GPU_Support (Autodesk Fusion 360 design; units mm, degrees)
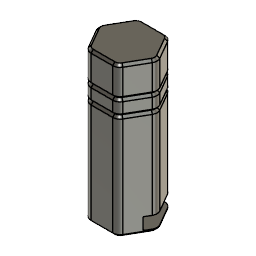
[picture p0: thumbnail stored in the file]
parameter "BodyL" = 28
parameter "HexR" = 7
parameter "Fillet" = 2
parameter "NutH" = 4
parameter "ThreadOffset" = 0.2
parameter "MagnetD" = 10
parameter "MagnetH" = 3
sketch "Sketch1" plane through (0, 0, 0) normal (0, 0, 1) x axis (1, 0, 0)
  line L1 (4.0415, 7) -> (8.0829, 0)
  line L2 (-4.0415, 7) -> (4.0415, 7)
  line L3 (-8.0829, 0) -> (-4.0415, 7)
  line L4 (-4.0415, -7) -> (-8.0829, 0)
  line L5 (4.0415, -7) -> (-4.0415, -7)
  line L6 (8.0829, 0) -> (4.0415, -7)
  line L7 (6.9744, -1.9201) -> (2.575, -4.46)
  line L8 (-2.575, 4.46) -> (1.8244, 7)
  circle C1 centre (0, 0) radius 5.15
  point P1 (0, 0)
  point P8 (0, 0)
  point P9 (0, 0)
  point P10 (2.575, -4.46)
  point P12 (1.8244, 7)
  point P11 (6.9744, -1.9201)
  coincident P1 P8
  horizontal L2
  coincident P1 P9
  coincident C1 P10
  tangent C1 L7
  coincident L2 P12
  parallel L7 L8
  equal L7 L8
  tangent C1 L8
  perpendicular L1 L7
  coincident L6 P11
  dimension "d1" distance P8 L6 = 7
  dimension "d36" diameter C1 = 10.3 (= "MagnetD + 0.3 mm")
extrude "Extrude1" new body sketch "Sketch1" profile of L1 L2 L3 L4 L5 L6 along normal blind 28 (= "BodyL")
fillet "Fillet1" radius 2 (= "Fillet")
sketch "Sketch1" plane through (0, 0, 28) normal (0, 0, 1) x axis (-1, 0, 0)
  line L1 (-7.5056, 1) -> (-4.6188, 6)
  line L2 (-4.6188, -6) -> (-7.5056, -1)
  line L3 (2.8868, -7) -> (-2.8868, -7)
  line L4 (7.5056, -1) -> (4.6188, -6)
  line L5 (4.6188, 6) -> (7.5056, 1)
  line L6 (-2.8868, 7) -> (2.8868, 7)
  arc A1 centre (5.7735, 0) radius 2 clockwise from (7.5056, 1) to (7.5056, -1)
  arc A2 centre (2.8868, 5) radius 2 clockwise from (2.8868, 7) to (4.6188, 6)
  arc A3 centre (-2.8868, 5) radius 2 clockwise from (-4.6188, 6) to (-2.8868, 7)
  arc A4 centre (-5.7735, 0) radius 2 clockwise from (-7.5056, -1) to (-7.5056, 1)
  arc A5 centre (-2.8868, -5) radius 2 clockwise from (-2.8868, -7) to (-4.6188, -6)
  arc A6 centre (2.8868, -5) radius 2 clockwise from (4.6188, -6) to (2.8868, -7)
extrude "Extrude1" new body sketch "Sketch1" profile of L1 L2 L3 L4 L5 L6 along normal blind 4 (= "NutH")
sketch "Sketch1" plane through (0, 0, 32) normal (0, 0, 1) x axis (-1, 0, 0)
  line L1 (7.5056, -1) -> (4.6188, -6)
  line L2 (4.6188, 6) -> (7.5056, 1)
  line L3 (-2.8868, 7) -> (2.8868, 7)
  line L4 (-7.5056, 1) -> (-4.6188, 6)
  line L5 (-4.6188, -6) -> (-7.5056, -1)
  line L6 (2.8868, -7) -> (-2.8868, -7)
  arc A1 centre (2.8868, -5) radius 2 clockwise from (4.6188, -6) to (2.8868, -7)
  arc A2 centre (5.7735, 0) radius 2 clockwise from (7.5056, 1) to (7.5056, -1)
  arc A3 centre (2.8868, 5) radius 2 clockwise from (2.8868, 7) to (4.6188, 6)
  arc A4 centre (-2.8868, 5) radius 2 clockwise from (-4.6188, 6) to (-2.8868, 7)
  arc A5 centre (-5.7735, 0) radius 2 clockwise from (-7.5056, -1) to (-7.5056, 1)
  arc A6 centre (-2.8868, -5) radius 2 clockwise from (-2.8868, -7) to (-4.6188, -6)
  circle C1 centre (0, 0) radius 4
  point P1 (0, 0)
  point P20 (0, 0)
  coincident P1 P20
  dimension "d14" diameter C1 = 8
extrude "Extrude1" new body sketch "Sketch1" profile of A1 L1 A2 L2 A3 L3 A4 L4 A5 L5 A6 L6 along normal blind 8
extrude "Extrude2" add sketch "Sketch1" profile of C1 against normal blind 27 (magnitude of "-BodyL + 1 mm")
thread "Thread1" ThreadOffset 0 ThreadLength 10
combine "Combine1"
combine "Combine1"
offset_faces "OffsetFaces1"
chamfer "Chamfer1" distance 0.6 distance 1
extrude "Extrude2" cut sketch "Sketch1" profile of L1 L2 L6 C1 L7 L8 blind 3.2 (= "MagnetH + 0.2 mm") from offset 0.8
sketch "Sketch2" plane through (-6.0622, -3.5, 0) normal (-0.866, -0.5, 0) x axis (0.5, -0.866, 0)
  line L1 (-2.8868, 0.6) -> (-2.8868, 27.4)
  line L2 (2.8868, 27.4) -> (2.8868, 0.6)
  line L3 (-5.15, 0.8) -> (5.15, 0.8)
  line L4 (-5.15, 4) -> (5.15, 4)
  line L5 (0, 0.8) -> (0, 4)
  line L6 (1.1547, 2.4) -> (0.5774, 1.4)
  line L7 (0.5774, 3.4) -> (1.1547, 2.4)
  line L8 (-0.5774, 3.4) -> (0.5774, 3.4)
  line L9 (-1.1547, 2.4) -> (-0.5774, 3.4)
  line L10 (-0.5774, 1.4) -> (-1.1547, 2.4)
  line L11 (0.5774, 1.4) -> (-0.5774, 1.4)
  line L12 (2.8868, 0.6) -> (-2.8868, 0.6)
  line L13 (-2.8868, 27.4) -> (2.8868, 27.4)
  point P10 (0, 4)
  point P11 (0, 0.8)
  point P18 (0, 2.4)
  midpoint L4 P10
  midpoint L3 P11
  midpoint L5 P18
  horizontal L8
  dimension "d42" distance P18 L11 = 1
extrude "Extrude3" cut sketch "Sketch2" profile of L6 L7 L8 L9 L10 L11 to an object
fillet "Fillet2" radius 0.2
joint "Assemble1" alignAngle 0 alignOffsetX 0 alignOffsetY 0 alignOffsetZ 4 (= "NutH") SlideMinimum 0 SlideMaximum 20 (= "BodyL - 8 mm")
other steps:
chamfer "Chamfer1" distance 0.6 distance 1
offset_faces "OffsetFaces1"
chamfer "Chamfer1" distance 0.6 distance 1
create_component "CreateComponent1"
create_component "CreateComponent2"
create_component "CreateComponent3"
joint_origin "JointOrigin3"
joint_origin "JointOrigin3"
